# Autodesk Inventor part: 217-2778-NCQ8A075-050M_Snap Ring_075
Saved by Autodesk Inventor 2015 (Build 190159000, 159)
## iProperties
Created: 2014-11
Part Number: 217-2778-NCQ8A075-050M_Snap Ring_075
Material: Generic
Document SubType Name: Modeling
Designer: User
Density: 1 g/cm^3
Appearance: Default
Author: User
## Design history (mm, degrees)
node "217-2778-NCQ8A075-050M_Snap Ring_075.ipt1"
node "Cut-Extrude1"
node "Base1"
